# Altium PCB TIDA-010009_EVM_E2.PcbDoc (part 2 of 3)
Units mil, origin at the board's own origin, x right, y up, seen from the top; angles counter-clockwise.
Board outline 4485 x 3050 mil, 4 copper layers (Top Layer, Signal Layer 1, Signal Layer 2, Bottom Layer), stack 61.634 mil thick; 216 components, 95 nets, 514 pads, 224 vias.
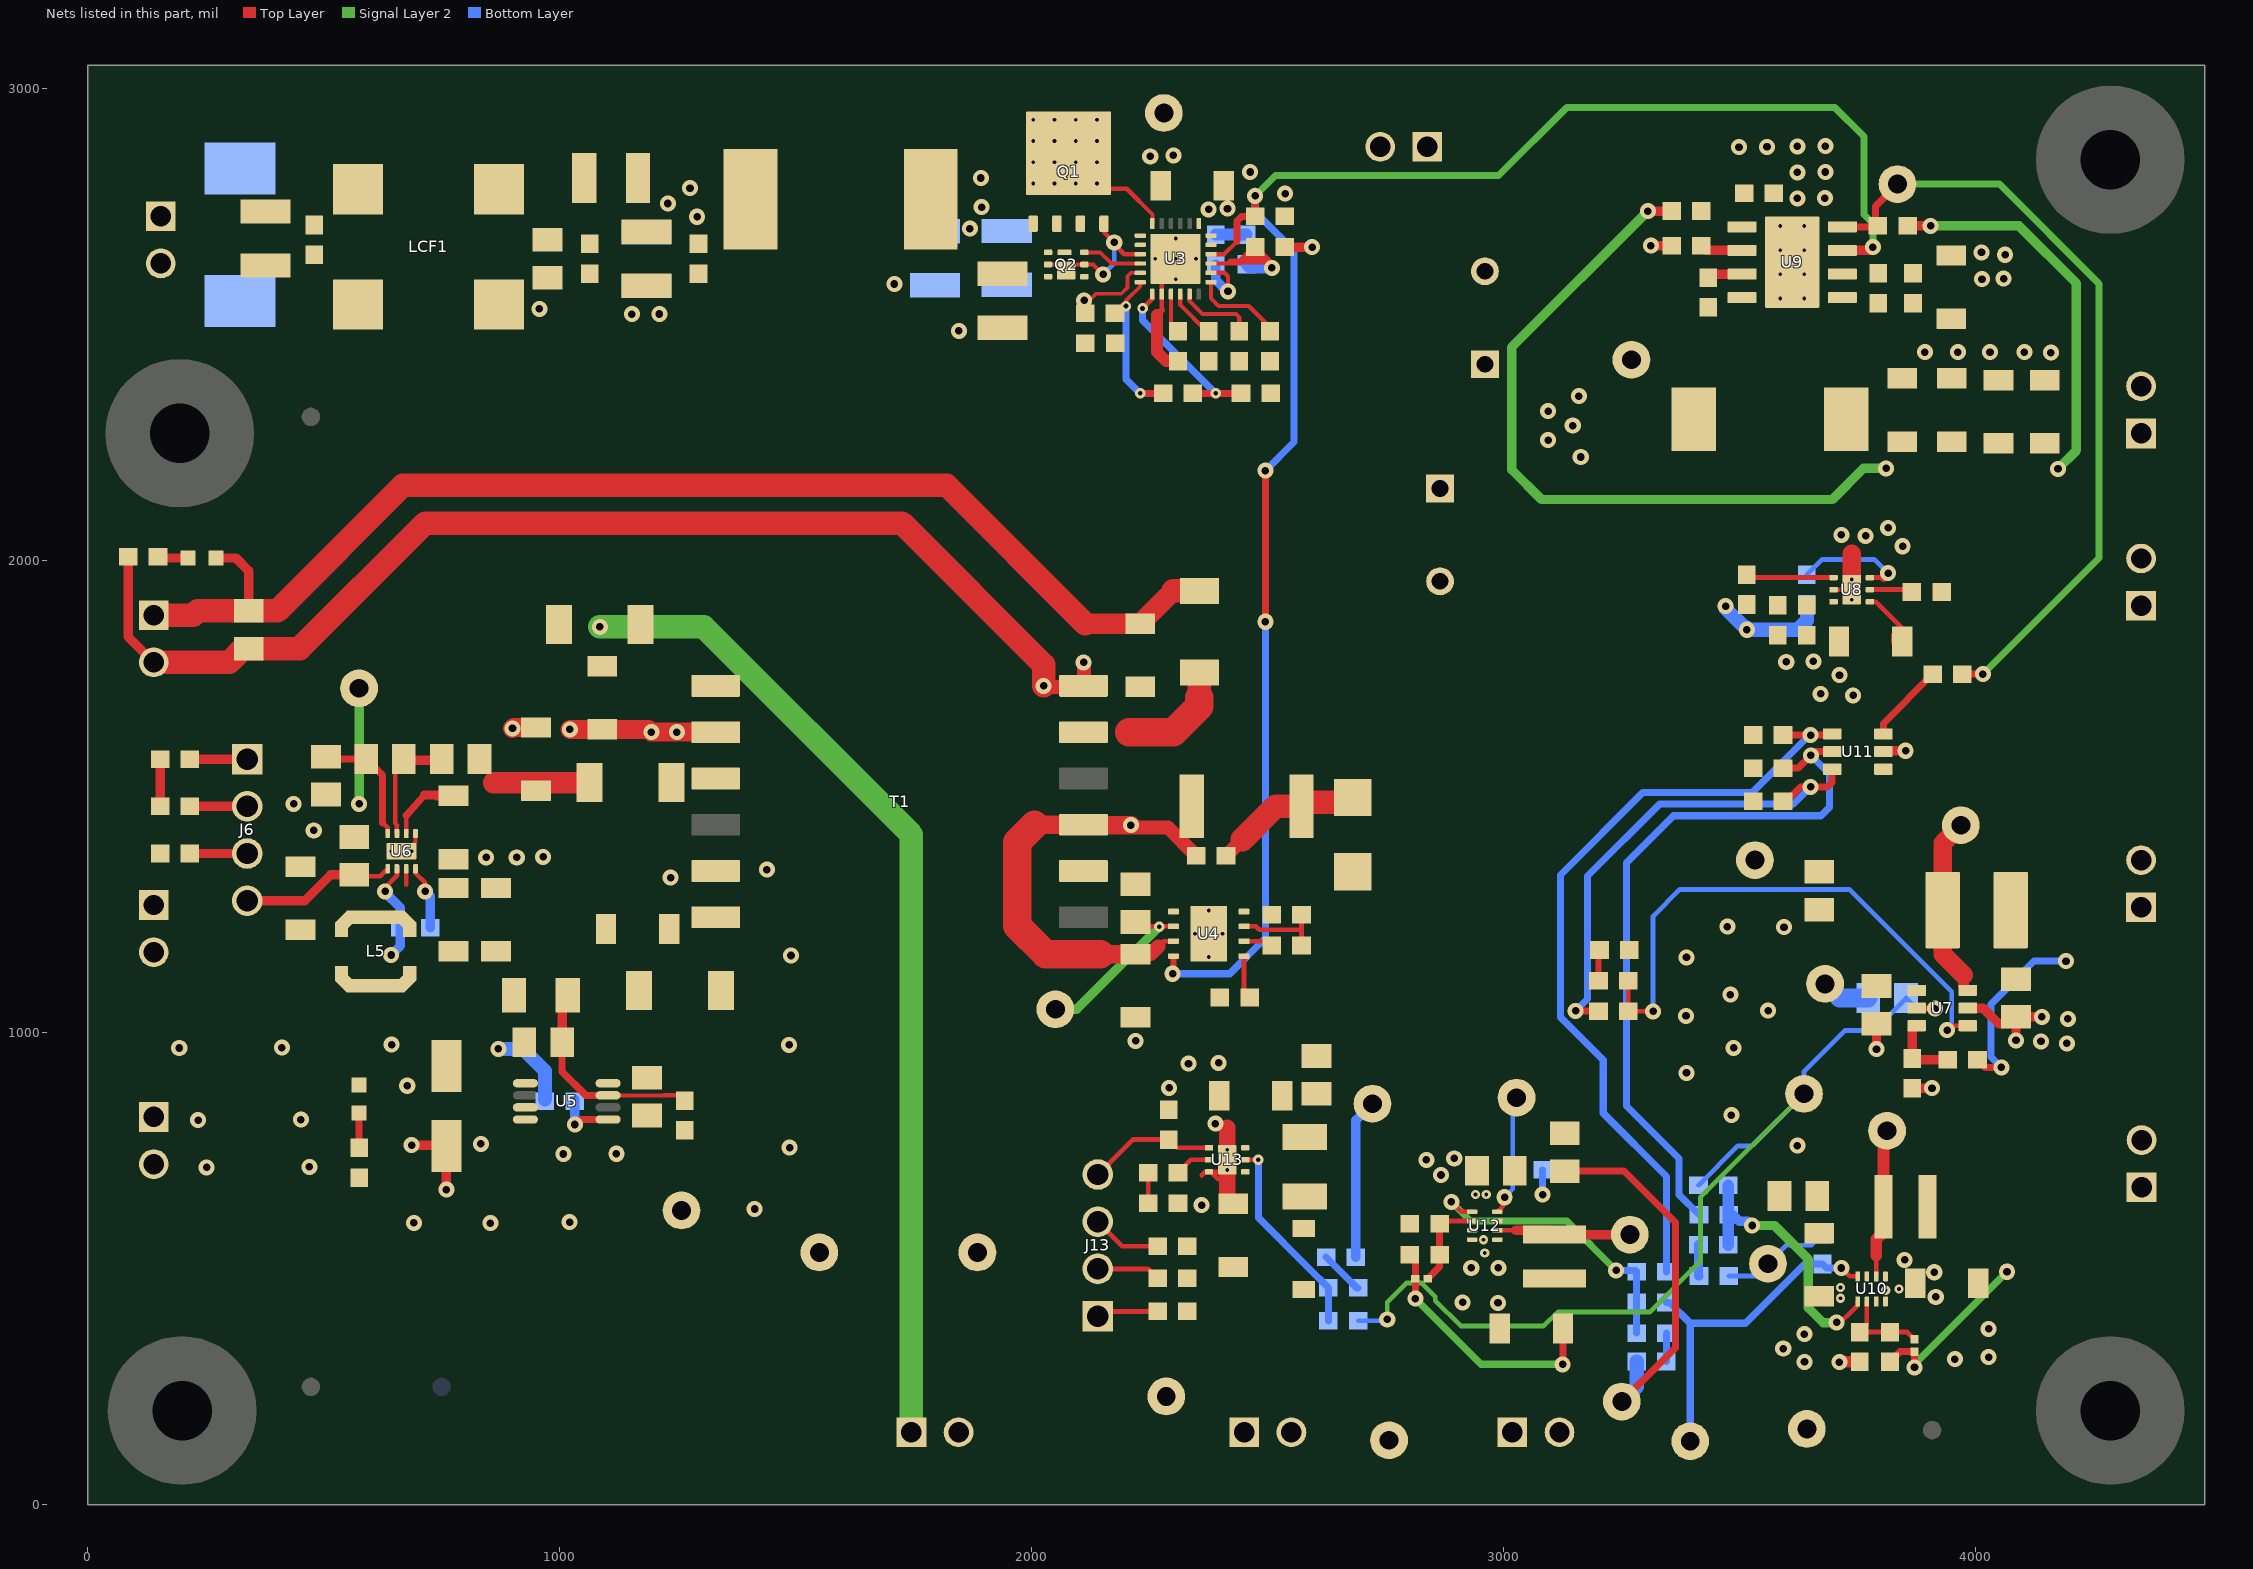
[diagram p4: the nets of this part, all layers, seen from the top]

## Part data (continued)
H5 H6 H7 H8: library part CMP-0003610-1, "Standoff, Hex, 0.5\"L #4-40 Nylon", Manufacturer=Keystone, Supplier Part Number 1=36-1902C-ND
H9 H10 H11 H12: library part CMP-0003620-1, "Bumpon, Hemisphere, 0.44 X 0.20, Clear", Manufacturer=3M, Supplier Part Number 1=SJ5303-7-ND
J1 J2 J3 J4 J5 J7 J8 J9 J10 J11 J12 J14: library part CMP-0054974-1, "Terminal Block, 2x1, 2.54mm, TH", Manufacturer="TE Connectivity", Supplier Part Number 1=A98333-ND
J6 J13: library part CMP-0054798-1, "Header, 2.54 mm, 4x1, Gold, TH", Manufacturer="Wurth Elektronik", Supplier Part Number 1=732-5317-ND
L5: library part CMP-0061350-2, "Inductor, Shielded Drum Core, Ferrite, 22 uH, 0.83 A, 0.36 ohm, SMD", Manufacturer=Coilcraft, Value1="0.36 ohm", Value2=0.83A, ValueDisplayed=22uH
L6: library part CMP-0058727-1, "Inductor, Wirewound, Ferrite, 2.2 uH, 2.6 A, 0.036 ohm, SMD", Manufacturer=MuRata, Supplier Part Number 1=490-7778-1-ND, Value1="0.036 ohm", Value2=2.6A, ValueDisplayed=2.2uH
L7 L9: library part CMP-0061147-1, "Inductor, Shielded, Composite, 470 nH, 3.5 A, 0.0076 ohm, SMD", Manufacturer=Coilcraft, Supplier Part Number 1=994-XFL4015-471MEC, Value1="0.0076 ohm", Value2=3.5A, ValueDisplayed=470nH
L8: library part CMP-0064666-2, "Inductor, Shielded, Metal Composite, 11 uH, 5.3 A, 0.014 ohm, SMD", Manufacturer="Wurth Elektronik", Supplier Part Number 1=732-2414-1-ND, Value1="0.014 ohm", Value2=5.3A, ValueDisplayed=11uH
L10: library part CMP-0058995-1, "Inductor, Shielded, Powdered Iron, 10 uH, 2 A, 0.2 ohm, SMD", Manufacturer="MuRata Toko", Value1="0.2 ohm", Value2=2A, ValueDisplayed=10uH
LCF1: "Coupled inductor, 11 µH, 2.5 A, 0.03 ohm, SMD", Manufacturer="Wurth Elektronik", PartNumber=744273102, Supplier Part Number 1=732-2960-1-ND, ValueDisplayed=11µH
LD1 LD2: library part CMP-0002874-1, "LED, Green, SMD", Color=green, Manufacturer=OSRAM, Supplier Part Number 1=475-2709-1-ND, Value1=W, Value2=1.7V
LF1: library part CMP-0057094-1, "Inductor, Drum Core, Ferrite, 4.7 uH, 6.8 A, 0.0155 ohm, SMD", Manufacturer=Bourns, Supplier Part Number 1=SRR1260-4R7YCT-ND, Value1="0.0155 ohm", Value2=6.8A, ValueDisplayed=4.7uH
Logo1: library part CMP-0074844-1
Logo3: library part CMP-0074847-1, "FCC_disclaimer"
Logo4: library part CMP-0074769-1
Logo5: library part CMP-0074839-1
Q1: library part CMP-0000960-2, "MOSFET, N-CH, 100 V, 13 A, DQJ0008A (VSONP-8)", Alternate Manufacturer=None, Manufacturer="Texas Instruments", Supplier Part Number 1=CSD19533Q5A-ND, Value2="27 nC"
Q2: library part CMP-0000248-1, "MOSFET, N-CH, 25 V, 5 A, DQK0006C (WSON-6)", Alternate Manufacturer=None, Manufacturer="Texas Instruments", Supplier Part Number 1=296-25260-1-ND, Value1=0.02, Value2="2 nC"
R1: library part CMP-0015361-2, "RES, 0, 5%, 0.25 W, 1210", Manufacturer=Rohm, Power_W=250mW, Supplier Part Number 1=RHM0.0BECT-ND, TempCo="20 ppm/C", Tolerance_%=5%, Value2=0.25W, Value_Code=0000, ValueDisplayed=0
R2 R18 R20 R25 R104: library part CMP-0023404-3, "RES, 10.0 k, 0.1%, 0.1 W, 0603", Manufacturer="Susumu Co Ltd", Power_W=100mW, Supplier Part Number 1=RG16P10.0KBCT-ND, TempCo="25 ppm/C", Tolerance_%=0.1%, Value2=0.1W, Value_Code=10k0, ValueDisplayed=10.0k
R19: library part CMP-0025329-3, "RES, 499 k, 0.5%, 0.1 W, 0603", Manufacturer="Yageo America", Power_W=100mW, TempCo="50 ppm/C", Tolerance_%=0.5%, Value2=0.1W, Value_Code=499k
R21: library part CMP-0023230-4, "RES, 665 k, 1%, 0.1 W, 0603", Manufacturer=Yageo, Power_W=100mW, Supplier Part Number 1=311-665KHRCT-ND, TempCo="100 ppm/C", Tolerance_%=1%, Value2=0.1W, Value_Code=665k
R22: library part CMP-0022804-5, "RES, 14.0 k, 1%, 0.1 W, 0603", Manufacturer=Yageo, Power_W=100mW, Supplier Part Number 1=311-14.0KHRCT-ND, TempCo="100 ppm/C", Tolerance_%=1%, Value2=0.1W, Value_Code=14k0, ValueDisplayed=14.0k
R23: library part CMP-0024107-3, "RES, 31.6 k, 0.1%, 0.1 W, 0603", Manufacturer="Yageo America", Power_W=100mW, TempCo="25 ppm/C", Tolerance_%=0.1%, Value2=0.1W, Value_Code=31k6, ValueDisplayed=31.6k
R24: library part CMP-0023508-3, "RES, 30.0 k, 0.1%, 0.1 W, 0603", Manufacturer="Susumu Co Ltd", Power_W=100mW, Supplier Part Number 1=RG16P30.0KBCT-ND, TempCo="25 ppm/C", Tolerance_%=0.1%, Value2=0.1W, Value_Code=30k0, ValueDisplayed=30.0k
R26: library part CMP-0023507-3, "RES, 3.00 k, 0.1%, 0.1 W, 0603", Manufacturer="Susumu Co Ltd", Power_W=100mW, Supplier Part Number 1=RG16P3.0KBCT-ND, TempCo="25 ppm/C", Tolerance_%=0.1%, Value2=0.1W, Value_Code=3k00, ValueDisplayed=3.00k
R27 R66 R67 R71 R72 R73 R74 R77 R78 R79 R80 R81: library part CMP-0023343-3, "RES, 0, 1%, 0.1 W, AEC-Q200 Grade 0, 0603", Manufacturer="Stackpole Electronics Inc", Power_W=100mW, Supplier Part Number 1=RMCF0603ZT0R00CT-ND, TempCo=ppm/C, Tolerance_%=1%, Value2=0.1W, Value_Code=0
R28: library part CMP-0021190-4, "RES, 365 k, 1%, 0.125 W, AEC-Q200 Grade 0, 0805", Manufacturer=Vishay-Dale, Power_W=125mW, Supplier Part Number 1=541-365KCCT-ND, TempCo="100 ppm/C", Tolerance_%=1%, Value2=0.125W, Value_Code=365k
R29: library part CMP-0015996-3, "RES, 6.2 k, 5%, 1 W, AEC-Q200 Grade 0, 2512", Manufacturer=Vishay-Dale, Power_W=1W, Supplier Part Number 1=541-6.2KXCT-ND, TempCo="200 ppm/C", Tolerance_%=5%, Value_Code=6k20, ValueDisplayed=6.2k
R30: library part CMP-0018159-2, "RES, 2.05 M, 1%, 0.25 W, 1206", Manufacturer="Yageo America", Power_W=250mW, Supplier Part Number 1=311-2.05MFRCT-ND, TempCo="100 ppm/C", Tolerance_%=1%, Value2=0.25W, Value_Code=2M05, ValueDisplayed=2.05M
R31 R44: library part CMP-0025892-5, "RES, 18 k, 5%, 0.1 W, 0603", Manufacturer=Yageo, Power_W=100mW, Supplier Part Number 1=311-18KGRCT-ND, TempCo="100 ppm/C", Tolerance_%=5%, Value2=0.1W, Value_Code=18k0, ValueDisplayed=18k
R32: library part CMP-0025409-3, "RES, 562 k, 0.5%, 0.1 W, 0603", Manufacturer="Yageo America", Power_W=100mW, TempCo="50 ppm/C", Tolerance_%=0.5%, Value2=0.1W, Value_Code=562k
R33: library part CMP-0023032-4, "RES, 330 k, 1%, 0.1 W, 0603", Manufacturer=Yageo, Power_W=100mW, Supplier Part Number 1=311-330KHRCT-ND, TempCo="100 ppm/C", Tolerance_%=1%, Value2=0.1W, Value_Code=330k
R34: library part CMP-0022739-4, "RES, 105 k, 1%, 0.1 W, 0603", Manufacturer=Yageo, Power_W=100mW, Supplier Part Number 1=311-105KHRCT-ND, TempCo="100 ppm/C", Tolerance_%=1%, Value2=0.1W, Value_Code=105k
R35: library part CMP-0024637-3, "RES, 12.1 k, 0.5%, 0.1 W, 0603", Manufacturer="Yageo America", Power_W=100mW, TempCo="50 ppm/C", Tolerance_%=0.5%, Value2=0.1W, Value_Code=12k1, ValueDisplayed=12.1k
R36: library part CMP-0022140-4, "RES, 1.05 M, 1%, 0.1 W, AEC-Q200 Grade 0, 0603", Manufacturer=Vishay-Dale, Power_W=100mW, Supplier Part Number 1=541-1.05MHCT-ND, TempCo="100 ppm/C", Tolerance_%=1%, Value2=0.1W, Value_Code=1M05, ValueDisplayed=1.05M
R37: library part CMP-0022291-4, "RES, 2.32 M, 1%, 0.1 W, AEC-Q200 Grade 0, 0603", Manufacturer=Vishay-Dale, Power_W=100mW, Supplier Part Number 1=541-2.32MHCT-ND, TempCo="100 ppm/C", Tolerance_%=1%, Value2=0.1W, Value_Code=2M32, ValueDisplayed=2.32M
R38: library part CMP-0023629-3, "RES, 1.00 k, 0.1%, 0.1 W, 0603", Manufacturer="Yageo America", Power_W=100mW, Supplier Part Number 1=YAG2179CT-ND, TempCo="10 ppm/C", Tolerance_%=0.1%, Value2=0.1W, Value_Code=1k00, ValueDisplayed=1.00k
R39: library part CMP-0025742-4, "RES, 1.8 M, 5%, 0.1 W, AEC-Q200 Grade 0, 0603", Manufacturer=Vishay-Dale, Power_W=100mW, Supplier Part Number 1=541-1.8MGCT-ND, TempCo="200 ppm/C", Tolerance_%=5%, Value2=0.1W, Value_Code=1M80, ValueDisplayed=1.8M
R40: library part CMP-0020876-3, "RES, 12.1, 1%, 0.125 W, AEC-Q200 Grade 0, 0805", Manufacturer=Vishay-Dale, Power_W=125mW, Supplier Part Number 1=541-12.1CCT-ND, TempCo="100 ppm/C", Tolerance_%=1%, Value2=0.125W, Value_Code=12R1, ValueDisplayed=12.1
R41: library part CMP-0018886-2, "RES, 1.50 k, 0.1%, 0.125 W, 0805", Manufacturer="Susumu Co Ltd", Power_W=125mW, Supplier Part Number 1=RG20P1.5KBCT-ND, TempCo="25 ppm/C", Tolerance_%=0.1%, Value2=0.125W, Value_Code=1k50, ValueDisplayed=1.50k
R42: library part CMP-0018914-2, "RES, 200 k, 0.1%, 0.125 W, 0805", Manufacturer="Susumu Co Ltd", Power_W=125mW, Supplier Part Number 1=RG20P200KBCT-ND, TempCo="25 ppm/C", Tolerance_%=0.1%, Value2=0.125W, Value_Code=200k
R43: library part CMP-0020780-3, "RES, 91, 5%, 0.125 W, AEC-Q200 Grade 0, 0805", Manufacturer=Panasonic, Power_W=125mW, Supplier Part Number 1=P91ACT-ND, TempCo="200 ppm/C", Tolerance_%=5%, Value2=0.125W, Value_Code=91R0, ValueDisplayed=91
R45 R51 R61 R65: library part CMP-0020616-3, "RES, 0, 5%, 0.125 W, AEC-Q200 Grade 0, 0805", Manufacturer=Panasonic, Power_W=125mW, Supplier Part Number 1=P0.0ACT-ND, TempCo="600 ppm/C", Tolerance_%=5%, Value2=0.125W, Value_Code=0000, ValueDisplayed=0
R46: library part CMP-0019302-2, "RES, 475 k, 0.5%, 0.1 W, 0805", Manufacturer="Susumu Co Ltd", Power_W=100mW, Supplier Part Number 1=RR12P475KDCT-ND, TempCo="25 ppm/C", Tolerance_%=0.5%, Value2=0.1W, Value_Code=475k
R47: library part CMP-0025299-2, "RES, 453 k, 0.5%, 0.1 W, 0603", Manufacturer="Yageo America", Power_W=100mW, TempCo="50 ppm/C", Tolerance_%=0.5%, Value2=0.1W, Value_Code=453k
R48 R52 R53 R54 R55 R56 R57 R58 R59 R62 R68 R69 R70 R82: library part CMP-0023363-3, "RES, 100 k, 0.1%, 0.1 W, AEC-Q200 Grade 0, 0603", Manufacturer=Panasonic, Power_W=100mW, Supplier Part Number 1=P100KDBCT-ND, TempCo="25 ppm/C", Tolerance_%=0.1%, Value2=0.1W, Value_Code=100k
R49 R100: library part CMP-0023509-3, "RES, 300 k, 0.1%, 0.1 W, 0603", Manufacturer="Susumu Co Ltd", Power_W=100mW, Supplier Part Number 1=RG16P300KBCT-ND, TempCo="25 ppm/C", Tolerance_%=0.1%, Value2=0.1W, Value_Code=300k
R50: library part CMP-0023024-4, "RES, 316 k, 1%, 0.1 W, 0603", Manufacturer=Yageo, Power_W=100mW, Supplier Part Number 1=311-316KHRCT-ND, TempCo="100 ppm/C", Tolerance_%=1%, Value2=0.1W, Value_Code=316k
R60: library part CMP-0023990-3, "RES, 24.9 k, 0.1%, 0.1 W, 0603", Manufacturer="Yageo America", Power_W=100mW, TempCo="25 ppm/C", Tolerance_%=0.1%, Value2=0.1W, Value_Code=24k9, ValueDisplayed=24.9k
R63: library part CMP-0025313-3, "RES, 475 k, 0.5%, 0.1 W, 0603", Manufacturer="Yageo America", Power_W=100mW, TempCo="50 ppm/C", Tolerance_%=0.5%, Value2=0.1W, Value_Code=475k
R64: library part CMP-0023766-3, "RES, 150 k, 0.1%, 0.1 W, 0603", Manufacturer="Yageo America", Power_W=100mW, TempCo="25 ppm/C", Tolerance_%=0.1%, Value2=0.1W, Value_Code=150k
R101: library part CMP-0022095-4, "RES, 187 k, 1%, 0.1 W, AEC-Q200 Grade 0, 0603", Manufacturer=Vishay-Dale, Power_W=100mW, Supplier Part Number 1=541-187KHCT-ND, TempCo="100 ppm/C", Tolerance_%=1%, Value2=0.1W, Value_Code=187k
R102: library part CMP-0022581-4, "RES, 71.5 k, 1%, 0.1 W, AEC-Q200 Grade 0, 0603", Manufacturer=Vishay-Dale, Power_W=100mW, Supplier Part Number 1=541-71.5KHCT-ND, TempCo="100 ppm/C", Tolerance_%=1%, Value2=0.1W, Value_Code=71k5, ValueDisplayed=71.5k
R103: library part CMP-0022494-4, "RES, 54.9 k, 1%, 0.1 W, AEC-Q200 Grade 0, 0603", Manufacturer=Vishay-Dale, Power_W=100mW, Supplier Part Number 1=541-54.9KHCT-ND, TempCo="100 ppm/C", Tolerance_%=1%, Value2=0.1W, Value_Code=54k9, ValueDisplayed=54.9k
T1: library part CMP-0082441-1, "Transformer, 75uH, SMT", Manufacturer="Wurth Elektronik", ValueDisplayed=75µH
TP8 TP12 TP13 TP14 TP16 TP17 TP19 TP20 TP21 TP23 TP24 TP26 TP27 TP28 TP29: library part CMP-0055137-1, "Test Point, Miniature, Red, TH", Color=Red, Manufacturer=Keystone, Supplier Part Number 1=36-5000-ND
TP9 TP10 TP11 TP15 TP18 TP22 TP25: library part CMP-0055138-1, "Test Point, Miniature, Black, TH", Color=Black, Manufacturer=Keystone, Supplier Part Number 1=36-5001-ND
U3: library part CMP-0080694-1, "4.5V - 60V, 6A 29mO eFuse with Reverse Polarity Protection, RGE0024H (VQFN-24)", Alternate Manufacturer="Texas Instruments", Alternate PartNumber=TPS26630RGET
U4: library part CMP-0078633-2, "70-V PSR Flyback Converter With 100-V, 1.2-A Power Switch and Ultra-Low IQ, NGU0008C (WSON-8)", Alternate Manufacturer="Texas Instruments", Alternate PartNumber=LM5180QNGUTQ1
U5: library part CMP-0071033-2, "Series of Adjustable Micropower Voltage Regulators, DGK0008A (VSSOP-8)", Manufacturer="Texas Instruments"
U6: library part CMP-0067088-2, "3V-17V, 300mA Buck Converter With Adjustable Enable Threshold And Hysteresis, DSG0008A (WSON-8)", Alternate Manufacturer="Texas Instruments", Alternate PartNumber=TPS62125DSGT
U7: library part CMP-0013280-3, "2-A High Efficiency Step-Down Converter in SOT Package, DDC0006A (SOT-6)", Alternate Manufacturer="Texas Instruments"
U8: library part CMP-0074216-4, "6.5 V/2.8 A eFuse with Overvoltage Clamp, DRV0006A (WSON-6)", Alternate Manufacturer="Texas Instruments", Alternate PartNumber=TPS25200DRVT
U9: library part CMP-0013272-2, "SIMPLE SWITCHER 3.8V to 36V 3A/2A Synchronous Step-Down Voltage Regulator, DDA0008J (SOIC-8)", Alternate Manufacturer="Texas Instruments", Alternate PartNumber=LMR33630ADDA
U10 U12: library part CMP-0065148-3, "1A Step-Down Converter With 1% Accuracy, DLC0008A (VSON-HR-8)", Alternate Manufacturer="Texas Instruments"
U11: library part CMP-0071684-1, "Power Sequencer, 6-pin SOT-23, 1000 Reel", Manufacturer="Texas Instruments", PackageTopMarking=F20A*XTT, PowerWise=N
U13: library part CMP-0067200-5, "1.2A Switch, High Voltage Boost Converter in 2x2mm QFN Package, DRV0006A (WSON-6)", Alternate Manufacturer="Texas Instruments", Alternate PartNumber=TPS61170DRVT
ZZ1: library part CMP-0003616-3
ZZ2: library part CMP-0077236-1
ZZ3: library part CMP-0077237-1
ZZ4: library part CMP-0077238-1

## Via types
v1: diameter 34, hole 16, Top Layer to Bottom Layer, 171 vias
v2: diameter 19.68, hole 7.87, Top Layer to Bottom Layer, 47 vias
v3: diameter 22, hole 10, Top Layer to Bottom Layer, 6 vias

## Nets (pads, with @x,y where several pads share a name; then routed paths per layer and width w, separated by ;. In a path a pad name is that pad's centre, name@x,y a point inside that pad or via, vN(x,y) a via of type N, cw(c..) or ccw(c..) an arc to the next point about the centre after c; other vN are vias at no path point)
1.2V/1A: C37.1 C39.1 J9.1 L7.2 R53.2 | length 378.3
  Top Layer w15: R53.2@3818.09,303.21 3839.89,325.01 C37.1@3870,325.01 v1(3870,291.44)
  Signal Layer 2 w15: v1(3870,291.44) 3870,298 v1(4066,494)
2.5V/1A: C48.1 C49.1 J10.2 L9.2 R63.2 | length 544.3
  Top Layer w15: R63.2@2801.01,530 2812.51,518.5 C48.1@2812.51,479 v1(2812.51,437.27) ; v1(3124.43,298) 3124.81,297.62 3125.38,297.62 C49.1@3125.38,373.7
  Signal Layer 2 w15: v1(2812.51,437.27) 2951.78,298 v1(3124.43,298)
3.3V/2A: C33.1 J8.1 L6.2 R47.2 | length 396.8
  Top Layer w15: R47.2@4003.5,943 4019.5,927 v1(4054,927)
  Bottom Layer w15: v1(4054,927) 4031.98,949.02 4031.98,1060.79 4123.19,1152 v1(4191,1152)
5V/3A: C3.1 C42.1 C43.1 C44.1 C45.1 C46.1 J12.1 L8.2 R45.1 R49.1 R51.1 R54.1 R55.2 R56.2 R57.2 R58.2 R61.1 R65.1 R100.1 TP14.1 U8.6 U11.1 | length 2624.5
  Top Layer w20: v1(3305.2,2741.05) R58.2@3355.55,2741.05 ; R54.1@3855.5,2709.62 v1(3904.38,2709.62) v1@3905,2709
  Signal Layer 2 w20: v1(3305.2,2741.05) 3017,2452.85 3017,2193 3080,2130 3696,2130 3762,2196 v1(3809.97,2196) ; v1(3904.38,2709.62) 4091.38,2709.62 4213,2588 4213,2234 v1(4174,2195)
  Bottom Layer w10: 3637,1869 3642,1874
  Bottom Layer w30: v1(3470,1904.02) 3470,1899.02 v1(3515,1854.02) ; v1@3515.02,1859 v1(3515,1854.02) ; 3637,1869 3622,1854 v1(3515,1854.02) ; 3642,1874 R100.1@3642,1907.5
5V/100mA: C31.2 C32.2 D5.1 J3.1 LD2.1 | length 2644.8
  Top Layer w20: LD2.1@271.53,2006 314,2006 341,1979 C31.2@341,1894
  Top Layer w43: 2113.07,1866.93 C32.2@2230,1866.93 2299.69,1936.61
  Top Layer w50: J3.1@140,1885 224,1885 233,1894 C31.2@341,1894 402,1894 668,2160 1820,2160 2113.07,1866.93 ; 2299.69,1936.61 D5.1@2355,1936.61
12V/250mA: C26.2 C27.1 D4.1 R40.2 U6.2 | length 361.1
  Top Layer w9.8: U6.2@674.84,1422.4 674.84,1460.44
  Top Layer w15: 674.84,1460.44 713.6,1504
  Top Layer w20: 713.6,1504 C27.1@753,1504 ; 740.07,1501.93 C27.1@762,1501.93
  Top Layer w45: 860,1530 D4.1@1063.39,1530
24V/100mA: C21.1 C24.1 J2.1 LD1.1 R30.1 R33.2 U5.1 | length 177.8
  Bottom Layer w30: v1(870.1,966) 922,966 968.95,919.05 R33.2@968.95,859.57
  other v1: 234.17,815.11 451.8,816.11 677,888 194,968 411.63,969 644,975
24V_INPUT: C1.2 C12.1 D1.2 J1.1 LCF1.3
-12V/100mA: C30.1 D6.2 J5.1 | length 2108.3
  Signal Layer 2 w50: v1(1085,1860) 1305,1860 1745,1420 J5.1@1745,154
EFUSE_OUT: C17.1 C18.1 C20.1 C23.2 C40.1 C55.1 C56.1 C101.1 J14.1 R18.2 R19.2 R20.2 R29.1 T1.3 U3.17 U3.18 U3.19 U4.3 U9.2 | length 1030.7
  Top Layer w9: 2268,1183 2279.25,1194.25 U4.3@2300.2,1194.25
  Top Layer w25: T1.3@2110.57,1438.98 T1.3@2111.58,1440
  Top Layer w30: v1(2210,1440) 2215,1435 2288.5,1435 C23.2@2348.5,1375 ; C20.1@2220,1166.93 2251.93,1166.93 2268,1183
  Top Layer w40: 2005.98,1440.98 T1.3@2109.57,1440.98 ; T1.3@2111.58,1440 v1(2210,1440) ; 2145,1166.71 2219.78,1166.71 C20.1@2220,1166.93
  Top Layer w60: 2005.98,1440.98 1969,1404 1969,1227.14 2029.21,1166.93 2144.78,1166.93 2145,1166.71
  Bottom Layer w25: R20.2@2389.76,2691.26 R19.2@2454.76,2691.26
  other v1: 3163,2220 3094,2255.84 3146.04,2286.42 3094,2317 3159.04,2348.78 4013,2597 4058.67,2598 4062,2648.5 4012,2653.39 2374.76,2744.76 2414.62,2745.99 2536.76,2777.77 2462.76,2823.77
EN: R77.1 U11.3 | length 169.8
  Top Layer w15: U11.3@3804.13,1633.4 3804.13,1655.63 R77.1@3908.5,1760
EN1: R71.1 R78.1 U7.1 | length 1205.4
  Top Layer w10: R78.1@3263.52,1110.64 R71.1@3263.52,1046.16 3315.63,1046.16 v1(3316.15,1045.64) ; v1(3939,1006.04) 3948.23,1015.26 U7.1@3982.92,1015.26 U7.1@3990.63,1015.26
  Bottom Layer w10: v1(3316.15,1045.64) 3316.15,1246.89 3373.14,1303.87 3732.13,1303.87 3948.99,1087.01 3948.99,1016.02 v1(3939,1006.04)
EN2: R66.2 R72.1 R79.1 U10.1 | length 578.4
  Top Layer w9.84: v1(3705.24,386.85) 3713.24,386.85 3738.09,411.7 3749.56,423.18 U10.1@3749.56,431
  Signal Layer 2 w20: v1(3526.18,592) 3573.76,592 3645,520.76 3645,417.67 3676.67,386 3704.38,386 v1(3705.24,386.85)
  Bottom Layer w20: R66.2@3476.5,615 3485.05,615 3499.05,601 3517.18,601 v1(3526.18,592)
  Bottom Layer w25: R72.1@3475.5,551 3475.5,614 R66.2@3476.5,615 3475.5,616 R79.1@3475.5,677
EN3: R67.2 R73.1 R80.1 U12.1 | length 647
  Top Layer w9.8: v1@2897,648.03 2890.97,642 v1(2889,642) 2909.77,621.23 U12.1@2933.13,621.23
  Signal Layer 2 w15: v1(2889,642) 2929.46,601.54 3133.31,601.54 v1(3238,496.85)
  Bottom Layer w15: v1(3238,496.85) 3278.65,496.85 R67.2@3281.5,494 R80.1@3281.5,429 R73.1@3281.5,364
EN4: R74.1 R81.1 U13.5 | length 430.3
  Top Layer w10: U13.5@2452.36,731.04 v3(2480.02,731.04)
  Bottom Layer w15: v3(2480.02,731.04) 2480.02,608.49 2588.44,500.06 2588.44,499.93 2628.38,460 R74.1@2628.5,460 R81.1@2628.5,390
FB1: C21.2 R30.2 R34.1 U5.7 | length 443.3
  Top Layer w9: U5.7@1102.6,867.8 1102.6,867.63 1221.63,867.63 1221.79,867.8 1253.7,867.8 R34.1@1265,856.5
  Top Layer w15: C21.2@1005.13,978 1005.13,917.78 1055.12,867.8 U5.7@1102.6,867.8 ; R30.2@1005.13,1059.91 R30.2@1016.22,1071
  Top Layer w20: C21.2@1005.13,978 R30.2@1005.13,1059.91
FB2: J6.4 R42.2 U6.5 | length 328.2
  Top Layer w9.84: R42.2@565,1335 568.31,1331.69 619.57,1331.69 U6.5@635.47,1347.6
  Top Layer w20: J6.4@338,1280 460,1280 515,1335 R42.2@565,1335
FB3: J13.4 R104.2 U13.1 | length 273.4
  Top Layer w10: J13.4@2140,700 2213.98,773.98 R104.2@2290.35,773.98 2307.7,756.63 U13.1@2375.59,756.63
Flag1: R55.1 R71.2 U11.6 | length 1040.7
  Top Layer w15: v1(3152.15,1046.64) R71.2@3198.15,1046.64 ; R55.1@3591.5,1491 3598.49,1491 3628.49,1521 v1(3650,1521) 3685,1521 3695,1531 3695,1557.73 U11.6@3695.87,1558.6
  Bottom Layer w15: v1(3152.15,1046.64) 3177.51,1071.99 3177.51,1332.11 3330.4,1485 3614,1485 v1(3650,1521)
Flag2: R56.1 R66.1 U11.5 | length 1533.2
  Top Layer w15: R56.1@3591.5,1561 3623.69,1561 v1(3650.7,1588.01) 3658.69,1596 U11.5@3695.87,1596
  Bottom Layer w15: R66.1@3413.5,615 3371.5,657 3371,657 3371,734 3260,845 3260,1360.48 3359.52,1460 3672,1460 3690,1478 3690,1548.71 v1(3650.7,1588.01)
Flag3: R57.1 R67.1 U11.4 | length 1692.1
  Top Layer w15: R57.1@3591.5,1631 v1(3650,1631) 3693.46,1631 U11.4@3695.87,1633.4
  Bottom Layer w15: R67.1@3344.5,494 3344.5,696.1 3210.66,829.93 3210.66,942.34 3119.78,1033.23 3119.78,1334.78 3294.7,1509.7 3526.6,1509.7 3647.9,1631 v1(3650,1631)
GND: C2.1 C3.2 C4.2 C5.2 C6.2 C7.1 C8.2 C9.2 C13.2 C14.2 C15.2 C16.1 C17.2 C18.2 C19.2 C20.2 C25.2 C26.1 C27.2 C28.2 C29.2 C30.2 C33.2 C34.2 C35.2 C38.2 C39.2 C40.2 C42.2 C43.2 C44.2 C45.2 C46.2 C47.2 C49.2 C50.2 C51.2 C55.2 C56.2 C57.2 C101.2 J4.2 J5.2 J7.2 J8.2 J9.2 J10.1 J11.2 J12.2 J14.2 LCF1.1 R23.1 R24.1 R25.1 R26.1 R27.1 R35.1 R42.1 R43.1 R48.1 R50.1 R59.1 R60.1 R64.1 R104.1 T1.8 TP10.1 TP11.1 TP15.1 TP18.1 TP22.1 TP25.1 U3.8 U3.25@2304.76,2639.76 U4.8 U4.9@2375,1210 U6.1 U6.9@665,1385 U7.2 U8.5 U8.7@3737,1939 U9.1 U9.9 U10.3 U10.4 U10.5 U11.2 U12.3 U12.4 U12.5 U13.3 U13.7@2413.98,731.04 | length 1842.4
  Top Layer w8: U6.9@662.02,1386 U6.9@675.84,1386 ; U6.9@665,1385 674.84,1385 U6.9@675.84,1386 ; U6.9@678,1386 U6.9@675.84,1386 ; U6.1@694.53,1422.4 694.53,1404.69 U6.9@675.84,1386 ; U3.25@2272.24,2613.24 U3.25@2301.76,2642.76
  Top Layer w9: 2275.24,2530.76 U3.8@2275.24,2564.96 2275.24,2610.24 v2(2304.76,2639.76) ; U4.8@2442.24,1257.24 U4.8@2449.8,1257.24
  Top Layer w10: 2359.97,698 2367.42,705.45 U13.3@2375.59,705.45 U13.3@2379.55,705.45 ; 2395,690 U13.3@2379.55,705.45 ; U13.7@2410.04,705.45 U13.3@2379.55,705.45 ; U8.5@3698.61,1939 U8.7@3737,1939
  Top Layer w14: 2265.23,2520.75 2275.24,2530.76
  Top Layer w20: R23.1@2536.26,2664.76 v1(2593.76,2664.77) ; v1@3310.87,2668.42 v1(3311.52,2667.77) C47.2@3355.55,2667.77 ; v1(3789.51,965.51) C34.2@3789.51,1019.33 ; U11.2@3803.13,1597.69 v1(3851.03,1597.69) ; R48.1@3865.55,882.87 v1(3907.13,882.87) ; U7.2@3982.92,1052.67 4015.34,1052.67 4048.68,1019.33 4070.52,1019.33 C33.2@4085,1033.81 ; v1(4085,984) C33.2@4085,1033.81 ; v1(4140,1033.81) C33.2@4085,1033.81
  Top Layer w25: 2265.23,2520.75 2265.23,2442.77 2284.73,2423.27 C19.2@2309.76,2423.27 ; v1(3711.09,302.7) 3711.59,303.21 R59.1@3754.09,303.21
  Top Layer w35: C4.2@2413.98,650.95 v2(2413.98,709.39) U13.7@2413.98,731.04 v2(2413.98,752.7) 2413.98,799.47
  Top Layer w39.37: U8.7@3737,1939 v2(3737,1960.65) 3737,2014.81 3737.19,2015
  Top Layer w40: v1(900,1645) 901.93,1646.93 C26.1@950,1646.93 ; v1(1021.65,1643.07) C30.2@1090,1643.07 1187.98,1643.07 v1(1194,1637.05) v1(1248,1637.05) T1.8@1330.43,1637.05
  Signal Layer 2 w20: v1(575,1485) TP11.1@575,1725
  other v1: 3637,303.21 3955.58,309 4026.91,313 3592,331 3636.59,362 4027.05,373 2987.73,428 2912.73,429 3915,441 3911.91,493 2931,502.22 2988.56,502.22 3849,519 2359.72,635 2867,699 2836,731 2895,734 3622,761 2389,807.72 2291,883.54 2332,935.06 2396,936.31 4193,978 4138,982 2220,983 4195,1029.81 844,1372 909,1372 965,1373 479,1429.04 436.24,1485 3739.86,1715 3671.18,1718 3711.1,1758 3598.3,1786 3655.67,1787 3845,2030.95 3766.51,2053 3715,2055 3814,2070 4159,2441 3892,2442 3962,2442 4030,2442 4102.63,2442 1845.44,2487 1153,2522.78 1211,2523 957,2534 1709,2586.46 3622,2768 3680,2768.39 3622,2822.99 3681.38,2823.77 2251,2857 2300,2859 3498.2,2876.27 3557.57,2877.05 3622,2877.99 3681.38,2878.76
  other v2: 3713.09,437.7 3809.09,454.7 3837.09,457.58 3713.09,460.7 2959.7,533.7 2956.83,561.7 2939.83,657.7 2962.83,657.7 2375,1160.79 2345.87,1210 2404.13,1210 2375,1259.21 643.35,1385 686.65,1385 3737,1917.35 3585.41,2555.84 3636.59,2555.84 2304.76,2596.46 3585.41,2607.03 3636.59,2607.03 2261.46,2639.76 2348.07,2639.76 3585.41,2658.21 3636.59,2658.21 2304.76,2683.07 3585.41,2709.39 3636.59,2709.39
GND1: C22.2 C24.2 C58.2 J2.2 R31.1 R34.2 T1.11 TP9.1 U5.3 U5.4 | length 168
  Top Layer w20: v1(686.46,762.35) 760.1,762.35 v1(760.1,668)
  other v1: 691,597.5 853,597 1021,599 1413,627 252,715 469.63,716 1007.63,743.5 1120,744 1487,757.16 833,765 1486,974.79 1490,1164 1235,1329 1439,1346
GND2: C31.1 C32.1 J3.2 R44.2 T1.6 | length 2549.1
  Top Layer w20: R44.2@86.01,2009 86.01,1838.99 J3.2@140,1785 ; v1(2025,1735) v1@2026.92,1733.08
  Top Layer w30: v1@2026.92,1733.08 2110.57,1733.08 v1@2110.57,1785
  Top Layer w40: J3.2@140,1785 J3.2@150,1785
  Top Layer w50: J3.2@150,1785 300,1785 C31.1@329,1814 ; C31.1@341,1814 449,1814 715,2080 1725,2080 2025,1780 v1(2025,1735)
  other v1: 2110,1785
NetC1_1: C1.1 C12.2 D1.1 J1.2 LCF1.4
NetC2_2: C2.2 C6.1 C14.1 LF1.1 R1.2
  other v1: 1291,2729 1229,2757 1276,2789.76
NetC5_1: C5.1 C13.1 C15.1 C16.2 LF1.2 Q1.1 Q1.2 Q1.3 Q2.4 Q2.7 R21.2 U3.5 | length 158.5
  Top Layer w8: R21.2@2113.27,2543.27 2135.77,2565.77 2189.76,2565.77 2202.76,2578.77 2202.76,2602.77 2210.23,2610.24 U3.5@2229.96,2610.24
  other v1: 2110.76,2551.96 1869,2704 1893.87,2749.28 1892.08,2811
NetC7_2: C7.2 C8.1 LCF1.2 R1.1
NetC9_1: C9.1 R2.1 | length 65
  Top Layer w10: C9.1@2246.77,639 R2.1@2246.77,704
NetC19_1: C19.1 U3.9 | length 84.8
  Top Layer w9: U3.9@2294.92,2564.96 2294.92,2501.1 C19.1@2309.76,2486.26
NetC22_1: C22.1 C58.1 D3.1 U5.8
NetC23_1: C23.1 D2.1 R29.2 | length 319.8
  Top Layer w30: C23.1@2411.5,1375 2446.14,1409.65
  Top Layer w50: 2446.14,1409.65 2516.5,1480 R29.2@2571.14,1480 2580.14,1489 2670.26,1489 D2.1@2680,1498.74
NetC25_1: C25.1 U4.5 | length 92.6
  Top Layer w10: U4.5@2449.8,1162.76 2449.8,1086.69 C25.1@2461.5,1075
NetC36_1: C36.1 U9.7 | length 64.2
  Top Layer w20: C36.1@3440.5,2607.62 U9.7@3504.7,2607.62
NetC36_2: C36.2 L8.1 TP16.1 U9.8
NetC37_2: C37.2 R53.1 R59.2 U10.2 | length 193.3
  Top Layer w9.84: R59.2@3754.09,366.2 3769.25,381.36 U10.2@3769.25,431
  Top Layer w10: R59.2@3754.09,366.2 R53.1@3818.09,366.2 3854.79,366.2 C37.2@3870,350.99
NetC47_1: C47.1 U9.6 | length 90.4
  Top Layer w20: C47.1@3418.54,2667.77 3428.7,2657.62 U9.6@3504.7,2657.62
NetC48_2: C48.2 R63.1 R64.2 U12.2 | length 199
  Top Layer w9.8: R64.2@2864,596 2869.54,601.54 U12.2@2933.13,601.54
  Top Layer w15: C48.2@2838.5,479 2864,504.5 R63.1@2864,530 R64.2@2864,596
NetD2_2: D2.2 R28.2 T1.2 U4.1
NetD3_2: D3.2 T1.12
NetD4_2: D4.2 T1.9
NetD5_2: D5.2 T1.5 | length 243.2
  Top Layer w50: 2355,1710 D5.2@2355,1763.39
  Top Layer w60: 2206.15,1637.05 2300.39,1637.05 2355,1691.65 2355,1710
NetD6_1: D6.1 T1.7
NetD7_2: D7.2 L10.2 U13.4
NetJ6_1: J6.1 R39.1 | length 121.5
  Top Layer w20: R39.1@216.5,1580 J6.1@338,1580
NetJ6_2: J6.2 R36.1 | length 121.5
  Top Layer w20: R36.1@216.5,1480 J6.2@338,1480
NetJ6_3: J6.3 R37.2 | length 121.5
  Top Layer w20: R37.2@216.5,1380 J6.3@338,1380
NetJ13_1: J13.1 R101.1 | length 130.6
  Top Layer w10: J13.1@2140,400 2145,400 2155,410 R101.1@2266.5,410
NetJ13_2: J13.2 R102.1 | length 134.8
  Top Layer w10: J13.2@2140,500 2246.5,500 R102.1@2266.5,480
NetJ13_3: J13.3 R103.1 | length 148
  Top Layer w10: J13.3@2140,600 2192,548 R103.1@2266.5,548
NetL5_1: L5.1 U6.7 | length 34.1
  Top Layer w9.84: U6.7@674.84,1347.6 674.84,1314.04 675.21,1313.68
NetL6_1: L6.1 TP12.1 U7.3 | length 374.5
  Top Layer w23.62: U7.3@3973.58,1099.4 3973.58,1123
  Top Layer w40: TP12.1@3968.26,1440 3929.95,1401.69 L6.1@3929.95,1260 3929.95,1166.63 3973.58,1123
NetL7_1: L7.1 TP17.1 U10.6 | length 318.2
  Top Layer w9.84: U10.6@3788.93,484.15 3788.93,527.7
  Top Layer w25: 3788.93,527.7 3788.93,562.7 3804.44,578.21 L7.1@3804.44,631.7 3804.44,785.19 TP17.1@3812,792.76
NetL9_1: L9.1 TP21.1 U12.6 | length 284.5
  Top Layer w9.8: U12.6@2986.28,581.86 3025,581.86
  Top Layer w20: 3025,581.86 3098.1,581.86 L9.1@3107.13,572.82 TP21.1@3267,572.82
NetLD1_2: LD1.2 R31.2 | length 74
  Top Layer w15: R31.2@575,756.5 LD1.2@575,830.47
NetLD2_2: LD2.2 R44.1 | length 64.7
  Top Layer w20: R44.1@149,2009 152,2006 LD2.2@212.47,2006
NetQ1_4: Q1.4 Q2.1 Q2.2 Q2.5 Q2.6 Q2.8 U3.3 | length 328.8
  Top Layer w9: Q2.5@2034.61,2627.8 2060.2,2627.8 Q2.8@2073,2615 2085.8,2627.8 Q2.2@2111.39,2627.8 2130.01,2627.8 v1(2151,2606.81) ; Q1.4@2153,2714.14 2153,2696.24 v1@2177.6,2671.64
  Top Layer w9.8: 2195.88,2649.61 U3.3@2229.96,2649.61
  Top Layer w10: v1@2175.73,2669.76 2195.88,2649.61
  Bottom Layer w9: v1(2151,2606.81) 2174.76,2630.57 v1(2174.76,2674.76)
NetQ1_5: Q1.5 Q1.6 Q1.7 Q1.8 Q1.9@2078,2863.75 U3.1 U3.2 U3.24 | length 176.7
  Top Layer w9: Q1.9@2120.76,2788.35 2201.17,2788.35 2255.55,2733.98 U3.24@2255.55,2714.57
  other v2: 2003,2799.22 2048,2799.22 2093,2799.22 2138,2799.22 2003,2844.22 2048,2844.22 2093,2844.22 2138,2844.22 2003,2889.22 2048,2889.22 2093,2889.22 2138,2889.22 2003,2934.22 2048,2934.22 2093,2934.22 2138,2934.22
NetQ2_3: Q2.3 U3.4 | length 128.3
  Top Layer w8: Q2.3@2111.39,2653.39 2145.26,2653.39 2168.72,2629.92 U3.4@2229.96,2629.92
NetR2_2: R2.2 U13.2 | length 77
  Top Layer w10: R2.2@2309.76,704 2336.81,731.04 U13.2@2375.59,731.04
NetR19_1: R19.1 R23.2 U3.15 | length 349.2
  Top Layer w9: U3.15@2379.57,2629.92 2438.42,2629.92 2441.42,2632.92
  Top Layer w15: 2421.61,2632.92 2441.42,2632.92 R23.2@2473.27,2664.76 2473.26,2663.26 R23.2@2486.26,2650.26 ; 2445.76,2635.27 2456,2635.27 ; 2456,2635.27 2494.26,2635.27 v1(2508.76,2620.77) 2508.76,2627.77 R23.2@2486.26,2650.26 ; 2456,2635.27 2470.99,2650.26 R23.2@2486.26,2650.26
  Bottom Layer w25: R19.1@2454.76,2628.27 2462.26,2620.77 v1(2508.76,2620.77)
NetR20_1: R20.1 U3.14 | length 140.7
  Top Layer w8: v1(2415.76,2570.77) 2415.76,2602.77
  Top Layer w9: U3.14@2379.57,2610.24 2408.29,2610.24 2415.76,2602.77
  Bottom Layer w20: R20.1@2389.76,2628.27 2389.76,2594.76 2413.76,2570.77 v1(2415.76,2570.77)
NetR21_1: R21.1 R22.2 U3.6 | length 344.8
  Top Layer w8: v3(2199.76,2539.76) 2199.76,2551.27 2229.96,2581.46 U3.6@2229.96,2590.55
  Top Layer w9: R21.1@2176.26,2522.76 R21.1@2176.26,2524.76 R21.1@2176.26,2527.76
  Top Layer w15: R21.1@2176.26,2522.76 2193.27,2539.76 v3(2199.76,2539.76) ; v3(2229.76,2354.76) R22.2@2278.27,2354.76
  Bottom Layer w15: v3(2199.76,2539.76) 2199.76,2384.76 v3(2229.76,2354.76)
NetR22_1: R22.1 R24.2 U3.7 | length 385
  Top Layer w9.8: v3(2234.76,2534.76) 2255.55,2555.55 U3.7@2255.55,2564.96
  Top Layer w15: R22.1@2341.26,2354.76 v3(2389.76,2354.76) R24.2@2443.27,2354.76
  Bottom Layer w15: v3(2234.76,2534.76) 2234.76,2509.76 v3(2389.76,2354.76)
NetR25_2: R25.2 U3.13 | length 185.1
  Top Layer w9: U3.13@2379.57,2590.55 2379.57,2556.1 2395.91,2539.76 2459.76,2539.76 R25.2@2504.76,2494.76
NetR26_2: R26.2 U3.10 | length 109.4
  Top Layer w9: U3.10@2314.61,2564.96 2314.61,2544.92 ; R26.2@2374.76,2486.26 2370.33,2486.26 2314.76,2541.82 ; 2314.61,2544.92 2314.61,2541.98 2314.76,2541.82 ; 2314.61,2544.92 2314.76,2544.76 2314.76,2541.82
NetR27_2: R27.2 U3.11 | length 164
  Top Layer w9: U3.11@2334.29,2564.96 2334.29,2550.24 2361.64,2522.89 2432.66,2522.89 2439.76,2515.79 R27.2@2439.76,2486.26
NetR28_1: R28.1 TP8.1 U4.2 | length 376.5
  Top Layer w9: R28.1@2220,1235 2229.25,1225.75 U4.2@2300.2,1225.75
  Signal Layer 2 w20: TP8.1@2050,1050 2095,1050 v3(2270,1225)
NetR32_1: R32.1 R35.2 U4.7 | length 187.9
  Top Layer w10: U4.7@2449.8,1225.75 2474.68,1225.75 2482.01,1218.43 2569.63,1218.43 ; R32.1@2571.5,1185 R35.2@2571.5,1250
NetR32_2: R32.2 U4.6 | length 62.5
  Top Layer w10: U4.6@2449.8,1194.25 2499.25,1194.25 R32.2@2508.5,1185
NetR33_1: R33.1 U5.5 | length 128.6
  Top Layer w15: v1(1031.94,806) 1042.56,816.61 U5.5@1102.6,816.61
  Bottom Layer w20: v1(1031.94,806) R33.1@1031.94,859.57
NetR38_1: R38.1 U6.8 | length 137.4
  Top Layer w9.84: U6.8@694.53,1347.6 694.53,1338.57 715,1318.09 v1(715,1300)
  Bottom Layer w20: v1(715,1300) 725.5,1289.5 R38.1@725.5,1223
NetR40_1: R40.1 R41.2 U6.3 | length 244.5
  Top Layer w9.8: U6.3@655.16,1422.4 655.16,1440.15
  Top Layer w10: 655.16,1440.15 651.38,1443.93 651.38,1557.38 R41.2@672,1578
  Top Layer w20: R41.2@672,1578 748,1578 R40.1@750,1580
NetR41_1: R41.1 R43.2 U6.4 | length 263.5
  Top Layer w9.8: 625,1445 635.47,1434.53 U6.4@635.47,1422.4
  Top Layer w15: R43.2@505,1585 510,1580 R41.1@590,1580 625,1545 625,1445
NetR47_1: R47.1 R48.2 U7.6 | length 149.3
  Top Layer w20: U7.6@3874.65,1015.26 3865.55,1006.17 R48.2@3865.55,945.86 3868.41,943 R47.1@3940.5,943
NetR49_2: R49.2 U8.4 | length 186.1
  Top Layer w10: R49.2@3515,1970.52 3520.93,1964.59 U8.4@3698.61,1964.59
NetR50_2: R50.2 U8.2 | length 91.2
  Top Layer w11: U8.2@3775.39,1939 3859.51,1939 R50.2@3864.5,1934.01
NetR58_1: R58.1 R60.2 U9.5
NetR68_2: R68.2 R72.2 | length 66.4
  Bottom Layer w20: R72.2@3412.5,551 3412.5,486 R68.2@3413.5,485
NetR69_2: R69.2 R73.2 | length 60
  Bottom Layer w15: R69.2@3344.5,304 R73.2@3344.5,364
NetR70_2: R70.2 R74.2 | length 95
  Bottom Layer w15: R70.2@2623.5,525 2623.63,525 2663.56,485.07 2663.56,484.94 2688.5,460 R74.2@2691.5,460
NetR78_2: R78.2 R82.2 | length 62.9
  Top Layer w12: R78.2@3200.53,1110.64 R82.2@3200.53,1173.51
NetR100_2: R100.2 U8.3 | length 235.9
  Top Layer w11.2: U8.3@3775.39,1964.59 v1@3804.59,1964.59
  Top Layer w18: v1@3804.59,1964.59 v1(3814,1974)
  Bottom Layer w10: R100.2@3642,1970.5 3674.5,2003 3785,2003 v1@3811.13,1976.87
PG: R54.2 R77.2 TP19.1 U9.4 | length 1670.9
  Top Layer w15: U9.4@3717.3,2707.62 R54.2@3790.5,2707.62 ; R54.2@3792.5,2709.62 3787,2715.12 3787,2752 3788,2752 TP19.1@3834,2798 ; R77.2@3971.5,1760 v1(4015,1760)
  Signal Layer 2 w15: TP19.1@3834,2798 4050.07,2798 4261.13,2586.94 4261.13,2006.13 v1(4015,1760)
PG1: R46.1 R79.2 R81.2 TP29.1 U7.5 | length 2063.8
  Top Layer w10: U7.5@3874.65,1052.67 v1@3911.91,1052.67
  Signal Layer 2 w10: v1(2753.11,393) 2753.11,429.75 2793.36,470 2826,470 2854.87,441.13 2854.87,432.95 2908.52,379.3 3084.77,379.3 3114,408.53 3309.07,408.53 3416.5,515.96 3416.5,651.5 TP29.1@3636,871
  Bottom Layer w10: R81.2@2691.5,390 2750.11,390 v1(2753.11,393) ; R79.2@3412.5,677 3495.94,760.43 3525.43,760.43 TP29.1@3636,871 3636,918.37 3722.63,1005 3783.26,1005 R46.1@3852.07,1073.81 3874.37,1051.51 v1(3913.07,1051.51)
PG2: R52.2 R80.2 TP20.1 U10.8 | length 736.1
  Top Layer w9.84: v1(3715,502) 3715,501.82 3732.67,484.15 U10.8@3749.56,484.15
  Bottom Layer w15: R80.2@3344.5,429 3351,429 3395,385 ; TP20.1@3395,135 3395,385 ; v1@3714.82,502 3683.5,502 R52.2@3675,510.5 3637.45,510.5 3511.95,385 3395,385
PG3: R62.2 TP23.1 U12.8 | length 262.6
  Top Layer w9.8: U12.8@2986.28,621.23 2997.33,632.28 2997.33,643.37 3002.13,648.17 3002.13,650.26 3003.13,651.26 3002.59,651.8 v1(3001.78,651.8) ; v1@3001.24,651.26 v1(3001.78,651.8) ; v1@3003.13,653.15 v1(3001.78,651.8)
  Bottom Layer w9.8: v1(3001.78,651.8) 3019.34,669.36 R62.2@3019.34,710 3019.34,855.08 TP23.1@3027,862.74
PGOOD: R18.1 U3.16 U4.4 U9.3 | length 3803.5
  Top Layer w9: U3.16@2379.57,2649.61 2407.6,2649.61 2434.76,2676.77
  Top Layer w11.81: v1@2300.2,1127.32 U4.4@2300.2,1162.76
  Top Layer w15: v1(2298.23,1125.35) v1@2300.2,1127.32 ; 2434.76,2676.77 2434.76,2719.77 2444.76,2729.77 R18.1@2473.27,2729.76 v1(2473.26,2773.27) ; v1(2495,1871) v1(2495,2191)
  Top Layer w20: U9.3@3717.3,2657.62 v1@3775,2657.62 ; v1@3775,2664.62 v1(3782,2664.62)
  Signal Layer 2 w15: v1(2473.26,2773.27) 2516.12,2816.13 2988.84,2816.13 3133.46,2960.75 3701.15,2960.75 3762.87,2899.03 3762.87,2733.74 3782,2714.61 v1(3782,2664.62)
  Bottom Layer w15: v1(2298.23,1125.35) 2419.35,1125.35 2495,1201 v1(2495,1871) ; v1@2473.26,2783.26 v1(2473.26,2773.27) 2473.26,2739.48 2555.87,2656.87 2555.87,2251.87 v1(2495,2191)
VDD_ENCODER1: C35.1 J7.1 U8.1 | length 139.8
  Top Layer w10: U8.1@3775.39,1913.41 3787.59,1913.41 3843.93,1857.07 C35.1@3843.93,1829
  Top Layer w20: C35.1@3829.93,1828 C35.1@3829.93,1842 ; C35.1@3839.93,1842 C35.1@3839.93,1847.87
VDD_ENCODER2: C4.1 D7.1 J11.1 R101.2 R102.2 R103.2 TP24.1
VDD_EXTERNAL: C28.1 C29.1 C57.1 J4.1 L5.2 R36.2 R37.1 R38.2 R39.2 U6.6 | length 314.6
  Top Layer w9.84: v1(630,1300) 630,1308.09 655.16,1333.25 U6.6@655.16,1347.6
  Top Layer w20: R36.2@153.5,1480 R39.2@153.5,1580
  Bottom Layer w20: v1(630,1300) 630,1297.5 662.5,1265 R38.2@662.5,1223 662.5,1184.5 v1(643,1165)
VIN1: C34.1 R45.2 R46.2 R82.1 TP28.1 U7.4 | length 61.2
  Bottom Layer w40: 3710.86,1073.81 R46.2@3772.07,1073.81
  other v1: 3482,826 3387,915.31 3487,968.26 3386,1036 3560,1047 3480,1081.23 3387,1160 3593.53,1224 3473.82,1225
VIN2: C38.1 R51.2 R52.1 R68.1 TP27.1 U10.7 | length 235.2
  Bottom Layer w10: R68.1@3476.5,485 3533.64,485 TP27.1@3559.64,511 3598.84,550.2 3651.7,550.2 R52.1@3675,573.5
VIN3: C50.1 R61.2 R62.1 R69.1 TP26.1 U12.7 | length 858.9
  Top Layer w15: R61.2@3129.13,707.17 3254.83,707.17 3364,598 3364,333 TP26.1@3250,219
  Bottom Layer w15: v1@3081,656 v1(3082.33,657.33) R62.1@3082.33,710
  Bottom Layer w30: TP26.1@3250,219 3281.5,250.5 R69.1@3281.5,304
VIN4: C51.1 L10.1 R65.2 R70.1 TP13.1 U13.6 | length 339.6
  Bottom Layer w20: R70.1@2686.5,525 2686.5,814.7 TP13.1@2721.8,850
pads on no net: FID1.1 FID2.1 FID3.1 FID4.1 FID5.1 FID6.1 H1.1 H2.1 H3.1 H4.1 H5.0 H6.0 H7.0 H8.0 H9.0 H10.0 H11.0 H12.0 Q1.9@2020.91,2809.22 Q1.9@2020.91,2879.3 Q1.9@2078,2809.22 Q1.9@2078,2845.83 Q1.9@2078,2879.3 Q1.9@2135.09,2809.22 Q1.9@2135.09,2879.3 Q2.0 T1.1 T1.4 T1.10 U3.12 U3.20 U3.21 U3.22 U3.23 U3.25@2277.4,2612.4 U3.25@2277.4,2667.13 U3.25@2332.13,2612.4 U3.25@2332.13,2667.13 U4.9@2375,1180.28 U4.9@2375,1239.72 U5.2 U5.6 U6.9@647.28,1385 U6.9@682.72,1385 U8.7@3737,1921.28 U8.7@3737,1956.72 U13.7@2413.98,713.33 U13.7@2413.98,748.76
